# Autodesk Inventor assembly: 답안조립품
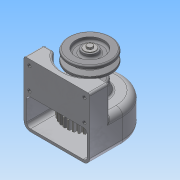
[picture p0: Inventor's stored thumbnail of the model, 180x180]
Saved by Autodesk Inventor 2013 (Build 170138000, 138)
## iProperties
Created: 2015-02
Part Number: 답안조립품
Document SubType Name: Assembly
Designer: Administrator
Author: Administrator
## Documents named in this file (14)
- C:\Documents and Settings\Administrator\바탕 화면\450214V1029\답안조립품.iam
- C:\Documents and Settings\Administrator\바탕 화면\450214V1029\1-본체.ipt
- C:\Documents and Settings\Administrator\바탕 화면\450214V1029\베어링 6001.ipt
- C:\Documents and Settings\Administrator\바탕 화면\450214V1029\축.ipt
- C:\Documents and Settings\Administrator\바탕 화면\450214V1029\5-스퍼기어.ipt
- C:\Documents and Settings\Administrator\바탕 화면\450214V1029\키5x5.ipt
- C:\Documents and Settings\Administrator\바탕 화면\450214V1029\축커버.ipt
- C:\Documents and Settings\Administrator\바탕 화면\450214V1029\오일실.ipt
- C:\Documents and Settings\Administrator\바탕 화면\450214V1029\M3x0.5.ipt
- C:\Documents and Settings\Administrator\바탕 화면\450214V1029\키4x4.ipt
- C:\Documents and Settings\Administrator\바탕 화면\450214V1029\와샤.ipt
- C:\Documents and Settings\Administrator\바탕 화면\450214V1029\4-v-벨트풀리.ipt
- C:\Documents and Settings\Administrator\바탕 화면\450214V1029\M5x0.8.ipt
- M5x0.8.ipt
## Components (7 placed, 4 different names)
1. 1-본체:1
2. 4-v-벨트풀리:1 — 각도:4
3. M5x0.8:1
4. M3x0.5:1
5. M3x0.5:2
6. M3x0.5:3
7. M3x0.5:4
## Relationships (1: Angle 1)
- 각도:4 [Angle]: 4-v-벨트풀리:1
